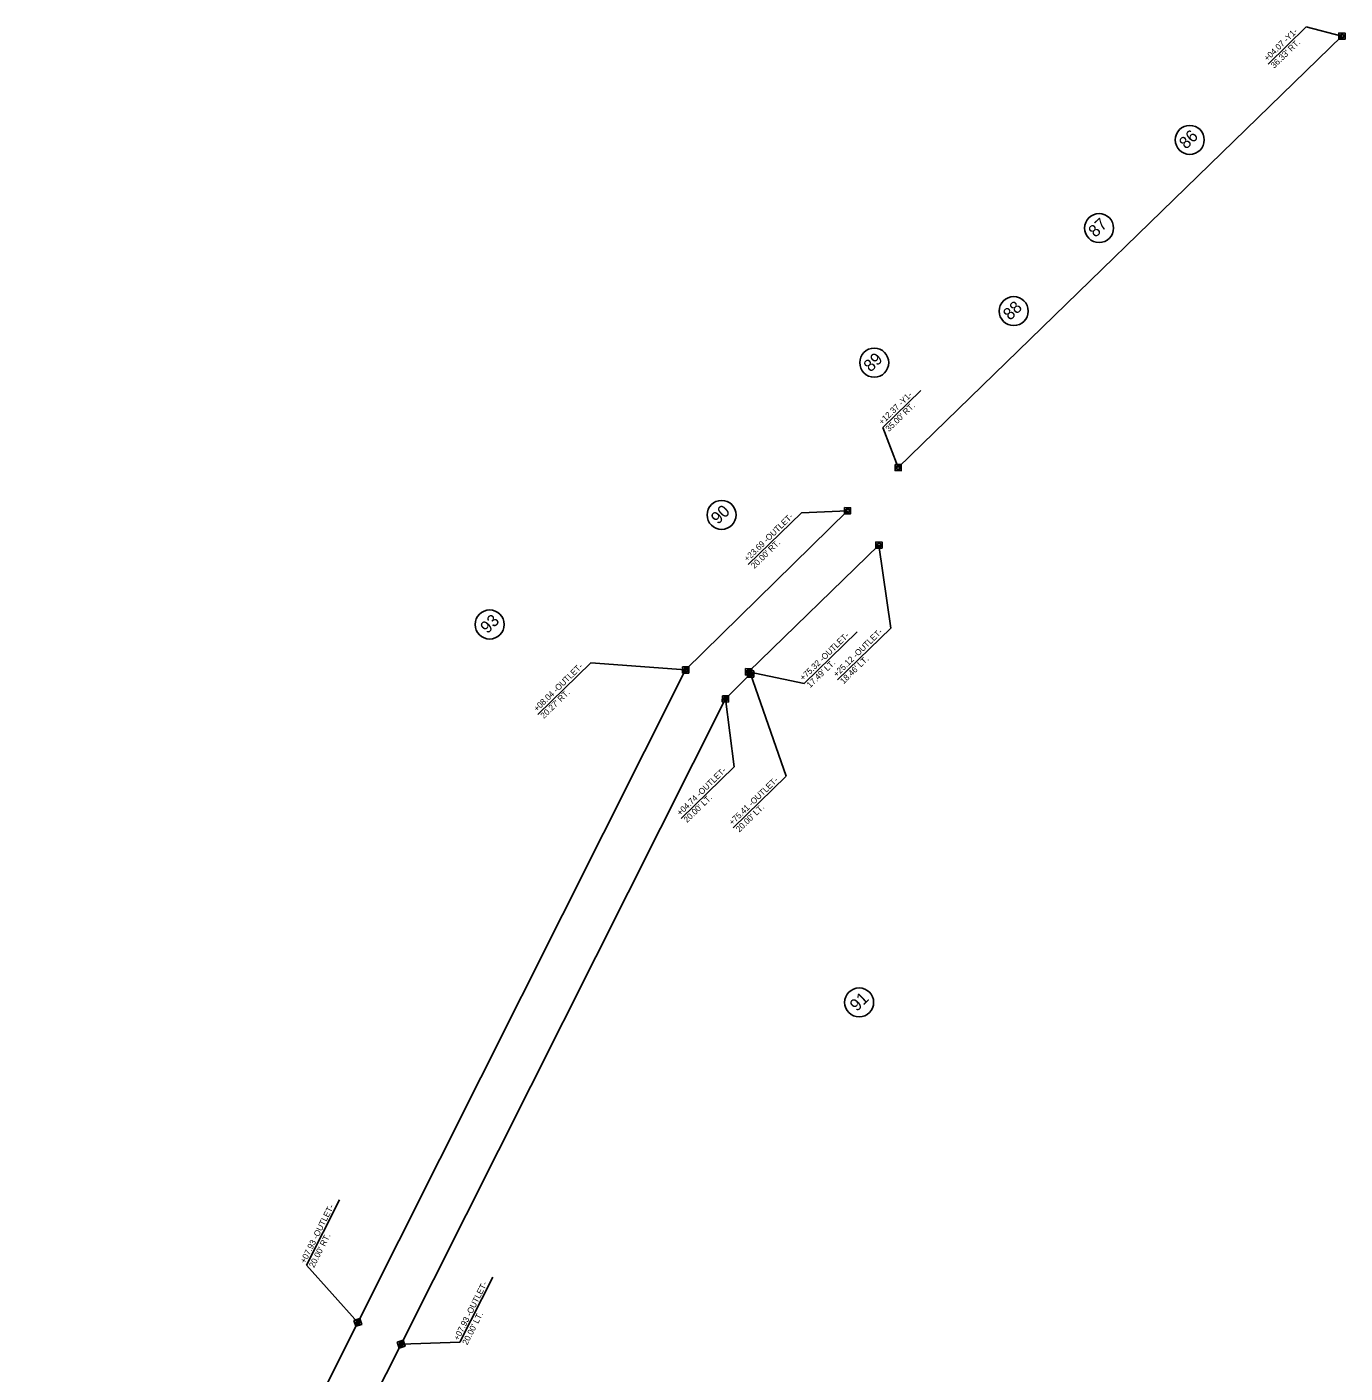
# Model space of a CAD drawing. Extents: x 2010883 to 2014849, y 442000 to 447413.
# Drawn here: x 2010992 to 2012081, y 442954 to 444066 of the extents above; entities that cross this region are included whole.
import ezdxf

# ---------------------------------------------------------------- set-up
doc = ezdxf.new("R2010")
doc.units = 0
for name, color, linetype in [('Prop Easement Permanent Drainage', 7, 'Continuous'), ('Prop Easement Permanent Drainage Station Offsets', 7, 'Continuous'), ('Prop Parcel Number CELL', 7, 'Continuous'), ('Prop Parcel Number Text', 7, 'Continuous'), ('Prop ROW Marker CELL', 7, 'Continuous'), ('Prop ROW Permanent Easement CELL', 7, 'Continuous')]:
    doc.layers.add(name, color=color, linetype=linetype)

msp = doc.modelspace()

# ---------------------------------------------------------------- linework, layer by layer
at = {"layer": 'Prop Easement Permanent Drainage'}
for p, q in [((2011712.2, 443702), (2012078.7, 444058.5)), ((2011536.6, 443534.8), (2011670.3, 443666.4)), ((2011588.6, 443533.3), (2011696.3, 443638)), ((2011265.8, 442995.8), (2011536.6, 443534.8)), ((2011569.4, 443510.9), (2011590.3, 443531.5)), ((2011590.3, 443531.5), (2011588.6, 443533.3)), ((2011301.5, 442977.8), (2011569.4, 443510.9)), ((2010992.4, 442452.8), (2011265.8, 442995.8)), ((2011036.4, 442451.2), (2011301.5, 442977.8))]:
    msp.add_line(p, q, dxfattribs=at)
at = {"layer": 'Prop Easement Permanent Drainage Station Offsets'}
for p, q in [((2012017.8, 444035.4), (2012049.3, 444066.1)), ((2012078.7, 444058.5), (2012049.3, 444066.1)), ((2011699.5, 443735.1), (2011731, 443765.8)), ((2011712.2, 443702), (2011699.5, 443735.1)), ((2011588.3, 443622), (2011632.2, 443664.7)), ((2011670.3, 443666.4), (2011632.2, 443664.7)), ((2011696.3, 443638), (2011706, 443569.4)), ((2011634.4, 443523.6), (2011678.3, 443566.3)), ((2011662, 443526.7), (2011706, 443569.4)), ((2011414.4, 443498.1), (2011458.3, 443540.8)), ((2011536.6, 443534.8), (2011458.3, 443540.8)), ((2011588.6, 443533.3), (2011634.4, 443523.6)), ((2011590.3, 443531.5), (2011619.7, 443447)), ((2011569.4, 443510.9), (2011576.7, 443454.9)), ((2011532.8, 443412.2), (2011576.7, 443454.9)), ((2011575.8, 443404.3), (2011619.7, 443447)), ((2011223.5, 443043.2), (2011250.6, 443097)), ((2011265.8, 442995.8), (2011223.5, 443043.2)), ((2011350.1, 442979.5), (2011377.2, 443033.3)), ((2011301.5, 442977.8), (2011350.1, 442979.5))]:
    msp.add_line(p, q, dxfattribs=at)
at = {"layer": 'Prop Parcel Number CELL'}
for p, q in [((2011953, 443972.7), (2011953, 443972.7)), ((2011878.1, 443899.9), (2011878.1, 443899.9)), ((2011807.6, 443831.3), (2011807.6, 443831.3)), ((2011692.4, 443788.7), (2011692.4, 443788.7)), ((2011566.3, 443662.9), (2011566.3, 443662.9)), ((2011374.7, 443572.4), (2011374.7, 443572.4)), ((2011679.9, 443260.2), (2011679.9, 443260.2))]:
    msp.add_line(p, q, dxfattribs=at)
for centre in [(2011953, 443972.7), (2011878.1, 443899.9), (2011807.6, 443831.3), (2011692.4, 443788.7), (2011566.3, 443662.9), (2011374.7, 443572.4), (2011679.9, 443260.2)]:
    msp.add_circle(centre, 12, dxfattribs=at)
at = {"layer": 'Prop ROW Marker CELL'}
for p, q in [((2012078.7, 444058.5), (2012078.7, 444058.5)), ((2011712.2, 443702), (2011712.2, 443702)), ((2011670.3, 443666.4), (2011670.3, 443666.4)), ((2011696.3, 443638), (2011696.3, 443638)), ((2011536.6, 443534.8), (2011536.6, 443534.8)), ((2011588.6, 443533.3), (2011588.6, 443533.3)), ((2011590.3, 443531.5), (2011590.3, 443531.5)), ((2011569.4, 443510.9), (2011569.4, 443510.9)), ((2011265.8, 442995.8), (2011265.8, 442995.8)), ((2011301.5, 442977.8), (2011301.5, 442977.8))]:
    msp.add_line(p, q, dxfattribs=at)
at = {"layer": 'Prop ROW Permanent Easement CELL'}
for points in [[(2012076.2, 444061.1), (2012081.3, 444061), (2012081.3, 444055.9), (2012076.2, 444056)], [(2012077.5, 444059.8), (2012080, 444059.7), (2012080, 444057.2), (2012077.5, 444057.2)], [(2011709.6, 443704.6), (2011714.7, 443704.5), (2011714.7, 443699.4), (2011709.6, 443699.5)], [(2011710.9, 443703.3), (2011713.4, 443703.3), (2011713.4, 443700.7), (2011710.9, 443700.8)], [(2011667.8, 443669), (2011672.9, 443668.9), (2011672.9, 443663.9), (2011667.8, 443663.9)], [(2011669.1, 443667.7), (2011671.6, 443667.7), (2011671.6, 443665.1), (2011669.1, 443665.2)], [(2011693.8, 443640.6), (2011698.9, 443640.5), (2011698.8, 443635.5), (2011693.7, 443635.5)], [(2011695.1, 443639.3), (2011697.6, 443639.3), (2011697.6, 443636.7), (2011695, 443636.8)], [(2011534.1, 443537.3), (2011539.2, 443537.3), (2011539.1, 443532.2), (2011534.1, 443532.3)], [(2011535.4, 443536.1), (2011537.9, 443536), (2011537.9, 443533.5), (2011535.3, 443533.5)], [(2011586.1, 443535.9), (2011591.2, 443535.8), (2011591.1, 443530.8), (2011586, 443530.8)], [(2011587.4, 443534.6), (2011589.9, 443534.6), (2011589.9, 443532), (2011587.3, 443532.1)], [(2011587.8, 443534.1), (2011592.9, 443534), (2011592.8, 443528.9), (2011587.7, 443529)], [(2011589.1, 443532.8), (2011591.6, 443532.7), (2011591.6, 443530.2), (2011589, 443530.2)], [(2011566.9, 443513.5), (2011572, 443513.4), (2011571.9, 443508.3), (2011566.8, 443508.4)], [(2011568.2, 443512.2), (2011570.7, 443512.2), (2011570.7, 443509.6), (2011568.1, 443509.6)], [(2011262.6, 442997.4), (2011267.4, 442999), (2011269, 442994.2), (2011264.2, 442992.6)], [(2011264.2, 442996.6), (2011266.6, 442997.4), (2011267.4, 442995), (2011265, 442994.2)], [(2011298.3, 442979.5), (2011303.2, 442981.1), (2011304.8, 442976.2), (2011299.9, 442974.6)], [(2011299.9, 442978.6), (2011302.4, 442979.4), (2011303.2, 442977), (2011300.7, 442976.2)]]:
    msp.add_lwpolyline(points, close=True, dxfattribs=at)

# ---------------------------------------------------------------- texts
at = {"layer": 'Prop Easement Permanent Drainage Station Offsets'}
for s, rotation, p in [('+04.07 -Y1-', 44.1983, (2012017.2, 444037.4)), ("36.33' RT.", 44.1983, (2012022.8, 444031.5)), ('+12.37 -Y1-', 44.1983, (2011698.9, 443737.1)), ("35.00' RT.", 44.1983, (2011704.6, 443731.3)), ('+23.69 -OUTLET-', 44.1983, (2011587.7, 443624)), ("20.00' RT.", 44.1983, (2011593.4, 443618.1)), ('+75.32 -OUTLET-', 44.1983, (2011633.8, 443525.6)), ('+25.12 -OUTLET-', 44.1983, (2011661.4, 443528.7)), ('+08.04 -OUTLET-', 44.1983, (2011413.8, 443500.1)), ("17.49' LT.", 44.1983, (2011639.5, 443519.7)), ("18.46' LT.", 44.1983, (2011667.1, 443522.9)), ("20.27' RT.", 44.1983, (2011419.5, 443494.3)), ('+04.74 -OUTLET-', 44.1983, (2011532.2, 443414.1)), ('+75.41 -OUTLET-', 44.1983, (2011575.2, 443406.2)), ("20.00' LT.", 44.1983, (2011537.8, 443408.3)), ("20.00' LT.", 44.1983, (2011580.9, 443400.4)), ('+07.93 -OUTLET-', 63.277, (2011222.3, 443044.1)), ("20.00' RT.", 63.277, (2011229.6, 443040.5)), ('+07.93 -OUTLET-', 63.277, (2011349, 442980.4)), ("20.00' LT.", 63.277, (2011356.2, 442976.7))]:
    msp.add_text(s, height=5, rotation=rotation, dxfattribs=at).set_placement(p)
at = {"layer": 'Prop Parcel Number Text'}
for s, p in [('86', (2011950, 443964.5)), ('87', (2011875.1, 443891.6)), ('88', (2011804.6, 443823.1)), ('89', (2011689.4, 443780.4)), ('90', (2011563.3, 443654.6)), ('93', (2011372.8, 443564.3)), ('91', (2011678, 443252.2))]:
    msp.add_text(s, height=10, rotation=44.1983, dxfattribs=at).set_placement(p)

doc.saveas('drawing.dxf')
